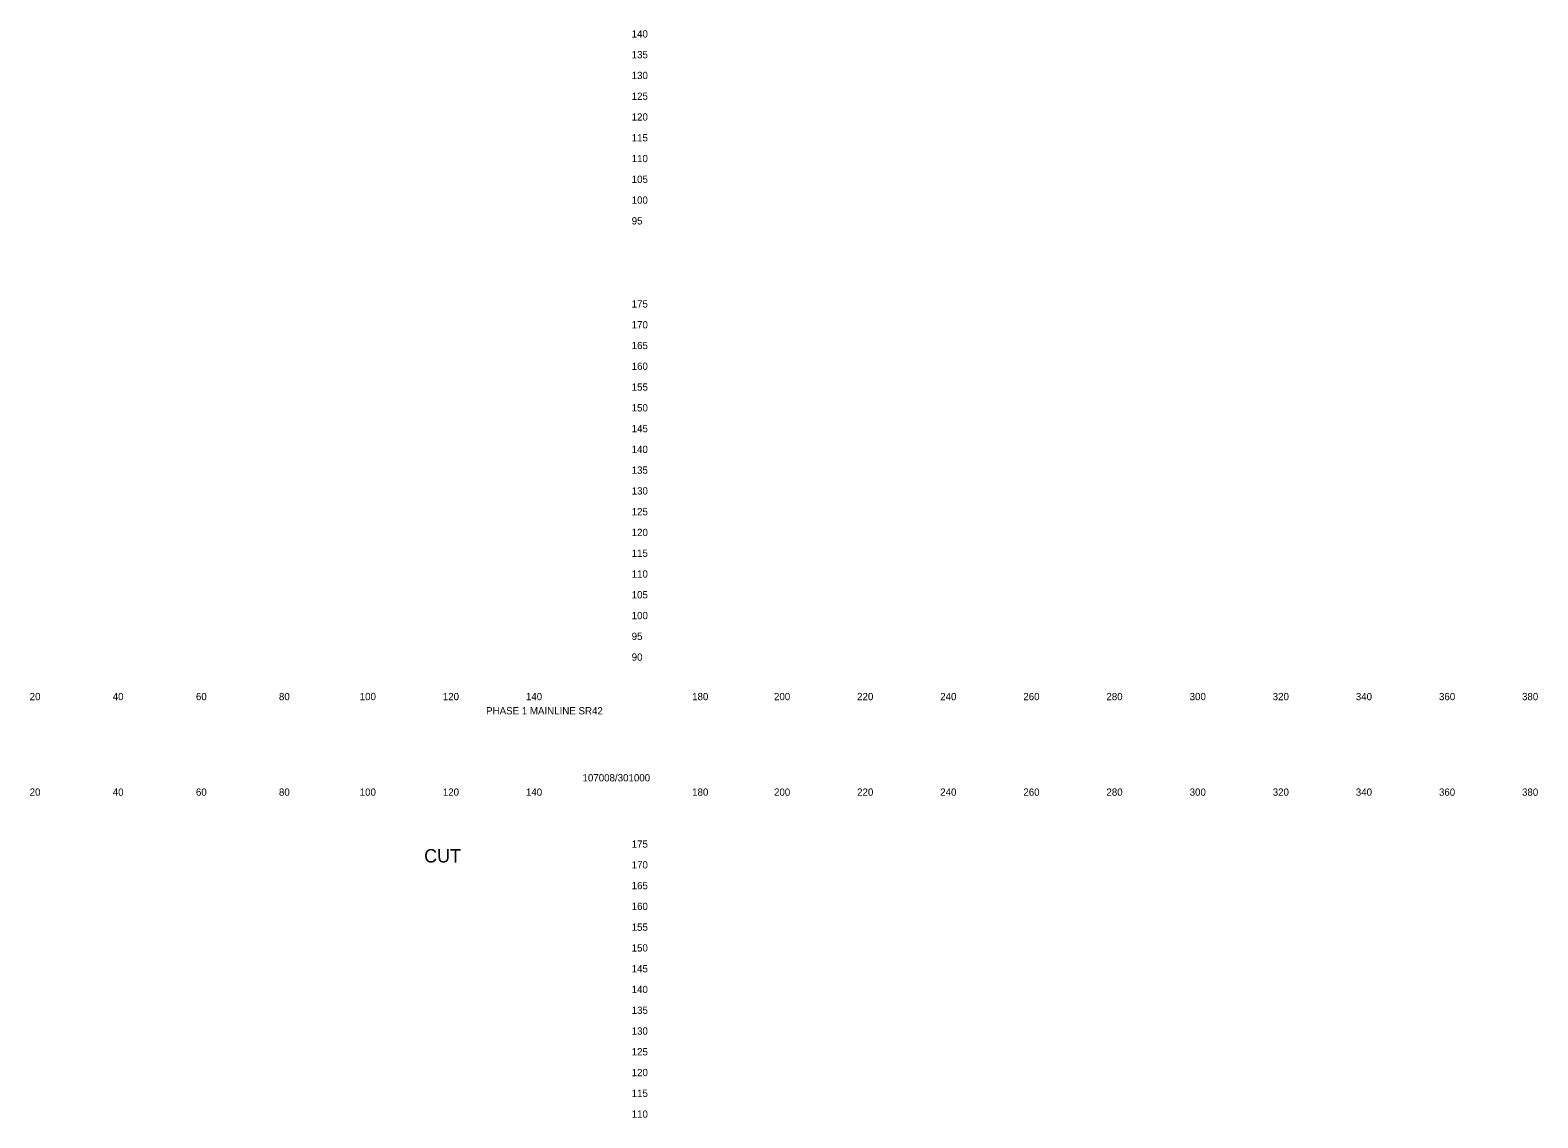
# Model space of a CAD drawing. Extents: x 21281 to 22024, y 6472 to 15198.
# Drawn here: x 21661.4 to 22024.2, y 11664.8 to 11926.6 of the extents above; entities that cross this region are included whole.
import ezdxf

# ---------------------------------------------------------------- set-up
doc = ezdxf.new("R2010")
doc.units = 0
doc.layers.add('XS_SHEET_LABELS_ELEVATION', color=7, linetype='Continuous')
doc.layers.add('XS_SHEET_LABELS_OFFSET', color=7, linetype='Continuous')

msp = doc.modelspace()

# ---------------------------------------------------------------- texts
at = {"layer": 'XS_SHEET_LABELS_ELEVATION'}
for s, p in [('  140  ', (21804.84, 11924.84)), ('  135  ', (21804.84, 11919.84)), ('  130  ', (21804.84, 11914.84)), ('  125  ', (21804.84, 11909.84)), ('  120  ', (21804.84, 11904.84)), ('  115  ', (21804.84, 11899.84)), ('  110  ', (21804.84, 11894.84)), ('  105  ', (21804.84, 11889.84)), ('  100  ', (21804.84, 11884.84)), ('  95  ', (21804.84, 11879.84)), ('  175  ', (21804.84, 11859.84)), ('  170  ', (21804.84, 11854.84)), ('  165  ', (21804.84, 11849.84)), ('  160  ', (21804.84, 11844.84)), ('  155  ', (21804.84, 11839.84)), ('  150  ', (21804.84, 11834.84)), ('  145  ', (21804.84, 11829.84)), ('  140  ', (21804.84, 11824.84)), ('  135  ', (21804.84, 11819.84)), ('  130  ', (21804.84, 11814.84)), ('  125  ', (21804.84, 11809.84)), ('  120  ', (21804.84, 11804.84)), ('  115  ', (21804.84, 11799.84)), ('  110  ', (21804.84, 11794.84)), ('  105  ', (21804.84, 11789.84)), ('  100  ', (21804.84, 11784.84)), ('  95  ', (21804.84, 11779.84)), ('  90  ', (21804.84, 11774.84)), ('  175  ', (21804.84, 11729.84)), ('  170  ', (21804.84, 11724.84)), ('  165  ', (21804.84, 11719.84)), ('  160  ', (21804.84, 11714.84)), ('  155  ', (21804.84, 11709.84)), ('  150  ', (21804.84, 11704.84)), ('  145  ', (21804.84, 11699.84)), ('  140  ', (21804.84, 11694.84)), ('  135  ', (21804.84, 11689.84)), ('  130  ', (21804.84, 11684.84)), ('  125  ', (21804.84, 11679.84)), ('  120  ', (21804.84, 11674.84)), ('  115  ', (21804.84, 11669.84)), ('  110  ', (21804.84, 11664.84))]:
    msp.add_text(s, height=1.75, dxfattribs=at).set_placement(p)
at = {"layer": 'XS_SHEET_LABELS_OFFSET'}
for s, height, p in [('  20  ', 1.75, (21659.95, 11765.34)), ('  40  ', 1.75, (21679.95, 11765.34)), ('  60  ', 1.75, (21699.97, 11765.34)), ('  80  ', 1.75, (21719.95, 11765.34)), ('  100  ', 1.75, (21739.39, 11765.34)), ('  120  ', 1.75, (21759.39, 11765.34)), ('  140  ', 1.75, (21779.39, 11765.34)), ('  180  ', 1.75, (21819.39, 11765.34)), ('  200  ', 1.75, (21839.1, 11765.34)), ('  220  ', 1.75, (21859.1, 11765.34)), ('  240  ', 1.75, (21879.1, 11765.34)), ('  260  ', 1.75, (21899.11, 11765.34)), ('  280  ', 1.75, (21919.1, 11765.34)), ('  300  ', 1.75, (21939.13, 11765.34)), ('  320  ', 1.75, (21959.13, 11765.34)), ('  340  ', 1.75, (21979.13, 11765.34)), ('  360  ', 1.75, (21999.14, 11765.34)), ('  380  ', 1.75, (22019.13, 11765.34)), ('PHASE 1 MAINLINE SR42', 1.75, (21771.11, 11761.92)), ('107008/301000', 1.75, (21794.31, 11745.79)), ('  20  ', 1.75, (21659.95, 11742.34)), ('  40  ', 1.75, (21679.95, 11742.34)), ('  60  ', 1.75, (21699.97, 11742.34)), ('  80  ', 1.75, (21719.95, 11742.34)), ('  100  ', 1.75, (21739.39, 11742.34)), ('  120  ', 1.75, (21759.39, 11742.34)), ('  140  ', 1.75, (21779.39, 11742.34)), ('  180  ', 1.75, (21819.39, 11742.34)), ('  200  ', 1.75, (21839.1, 11742.34)), ('  220  ', 1.75, (21859.1, 11742.34)), ('  240  ', 1.75, (21879.1, 11742.34)), ('  260  ', 1.75, (21899.11, 11742.34)), ('  280  ', 1.75, (21919.1, 11742.34)), ('  300  ', 1.75, (21939.13, 11742.34)), ('  320  ', 1.75, (21959.13, 11742.34)), ('  340  ', 1.75, (21979.13, 11742.34)), ('  360  ', 1.75, (21999.14, 11742.34)), ('  380  ', 1.75, (22019.13, 11742.34)), ('CUT', 3.222, (21756.2, 11726.27))]:
    msp.add_text(s, height=height, dxfattribs=at).set_placement(p)

doc.saveas('drawing.dxf')
